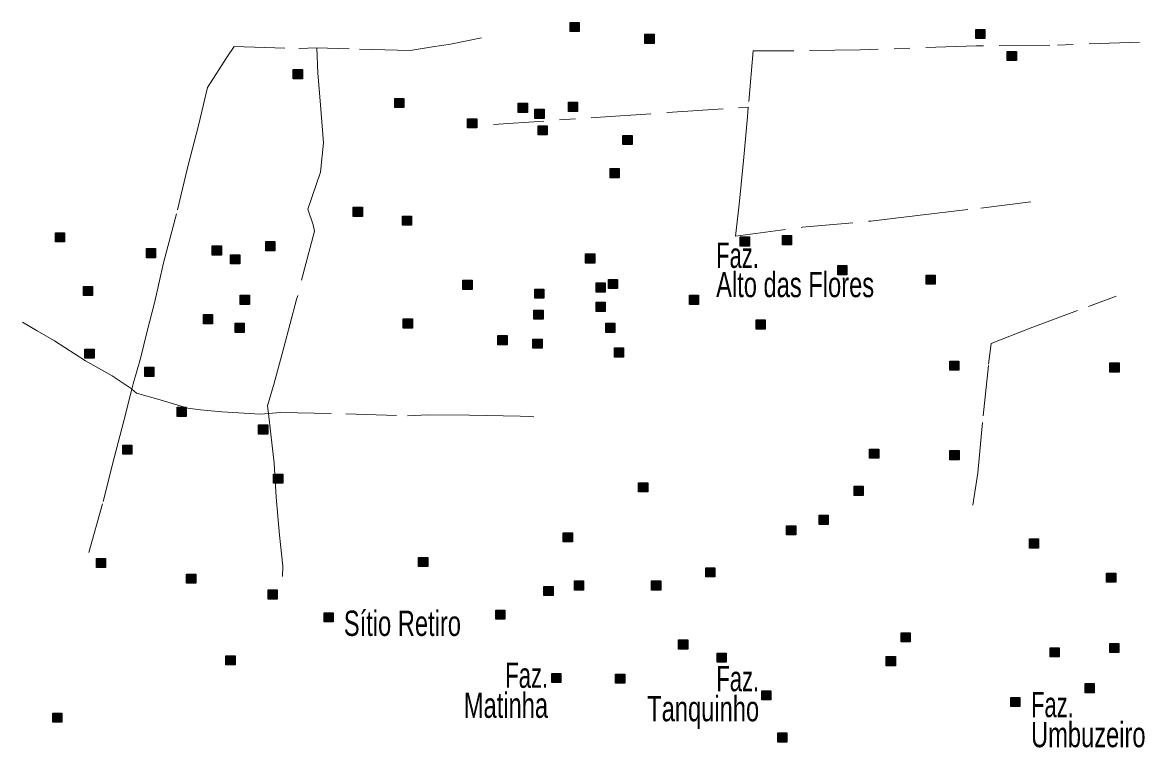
# Model space of a CAD drawing. Extents: x 445.6 to 500, y 8618.1 to 8673.4.
# Drawn here: x 445.63 to 452.73, y 8634.59 to 8639.18 of the extents above; entities that cross this region are included whole.
import ezdxf
from ezdxf.enums import TextEntityAlignment as Align

# ---------------------------------------------------------------- set-up
doc = ezdxf.new("R2010")
doc.units = 0
doc.header["$LTSCALE"] = 0.064
doc.linetypes.add('DOT_DASHED', pattern=[7.7, 5, -1.2, 0.3, -1.2])
doc.layers.add('2', color=7, linetype='Continuous', lineweight=25)
doc.layers.add('22', color=7, linetype='DOT_DASHED', lineweight=13)
doc.layers.add('61', color=7, linetype='Continuous')

msp = doc.modelspace()

# ---------------------------------------------------------------- hatches: boundary and pattern name
at = {"layer": '2'}
for points in [[(449.0969, 8639.1795), (449.1549, 8639.1795), (449.1549, 8639.1215), (449.0969, 8639.1215)], [(451.6615, 8639.1354), (451.7195, 8639.1354), (451.7195, 8639.0774), (451.6615, 8639.0774)], [(449.5698, 8639.105), (449.6278, 8639.105), (449.6278, 8639.047), (449.5698, 8639.047)], [(451.8608, 8638.9965), (451.9188, 8638.9965), (451.9188, 8638.9385), (451.8608, 8638.9385)], [(447.3463, 8638.8814), (447.4043, 8638.8814), (447.4043, 8638.8234), (447.3463, 8638.8234)], [(447.9881, 8638.6985), (448.0461, 8638.6985), (448.0461, 8638.6405), (447.9881, 8638.6405)], [(448.7693, 8638.668), (448.8273, 8638.668), (448.8273, 8638.61), (448.7693, 8638.61)], [(449.0868, 8638.6748), (449.1448, 8638.6748), (449.1448, 8638.6168), (449.0868, 8638.6168)], [(448.4484, 8638.5697), (448.5064, 8638.5697), (448.5064, 8638.5117), (448.4484, 8638.5117)], [(448.874, 8638.6307), (448.932, 8638.6307), (448.932, 8638.5727), (448.874, 8638.5727)], [(448.8943, 8638.5257), (448.9523, 8638.5257), (448.9523, 8638.4677), (448.8943, 8638.4677)], [(449.4313, 8638.4647), (449.4893, 8638.4647), (449.4893, 8638.4067), (449.4313, 8638.4067)], [(449.3503, 8638.2547), (449.4083, 8638.2547), (449.4083, 8638.1967), (449.3503, 8638.1967)], [(447.7262, 8638.0097), (447.7842, 8638.0097), (447.7842, 8637.9517), (447.7262, 8637.9517)], [(448.0366, 8637.9541), (448.0946, 8637.9541), (448.0946, 8637.8961), (448.0366, 8637.8961)], [(445.8421, 8637.8485), (445.9001, 8637.8485), (445.9001, 8637.7905), (445.8421, 8637.7905)], [(447.1721, 8637.793), (447.2301, 8637.793), (447.2301, 8637.735), (447.1721, 8637.735)], [(450.1728, 8637.8226), (450.2308, 8637.8226), (450.2308, 8637.7646), (450.1728, 8637.7646)], [(450.4392, 8637.8313), (450.4972, 8637.8313), (450.4972, 8637.7733), (450.4392, 8637.7733)], [(446.4184, 8637.7485), (446.4764, 8637.7485), (446.4764, 8637.6905), (446.4184, 8637.6905)], [(446.834, 8637.7652), (446.892, 8637.7652), (446.892, 8637.7072), (446.834, 8637.7072)], [(446.9504, 8637.7096), (447.0084, 8637.7096), (447.0084, 8637.6516), (446.9504, 8637.6516)], [(449.1948, 8637.7151), (449.2528, 8637.7151), (449.2528, 8637.6571), (449.1948, 8637.6571)], [(450.7898, 8637.641), (450.8478, 8637.641), (450.8478, 8637.583), (450.7898, 8637.583)], [(451.348, 8637.5812), (451.406, 8637.5812), (451.406, 8637.5232), (451.348, 8637.5232)], [(446.0194, 8637.5095), (446.0774, 8637.5095), (446.0774, 8637.4515), (446.0194, 8637.4515)], [(448.4189, 8637.5484), (448.4769, 8637.5484), (448.4769, 8637.4904), (448.4189, 8637.4904)], [(449.2613, 8637.5317), (449.3193, 8637.5317), (449.3193, 8637.4737), (449.2613, 8637.4737)], [(449.3388, 8637.554), (449.3968, 8637.554), (449.3968, 8637.496), (449.3388, 8637.496)], [(447.0113, 8637.4539), (447.0693, 8637.4539), (447.0693, 8637.3959), (447.0113, 8637.3959)], [(448.8733, 8637.4928), (448.9313, 8637.4928), (448.9313, 8637.4348), (448.8733, 8637.4348)], [(449.8518, 8637.4534), (449.9098, 8637.4534), (449.9098, 8637.3954), (449.8518, 8637.3954)], [(448.8678, 8637.3594), (448.9258, 8637.3594), (448.9258, 8637.3014), (448.8678, 8637.3014)], [(449.2613, 8637.4094), (449.3193, 8637.4094), (449.3193, 8637.3514), (449.2613, 8637.3514)], [(446.7786, 8637.3316), (446.8366, 8637.3316), (446.8366, 8637.2736), (446.7786, 8637.2736)], [(448.0421, 8637.3038), (448.1001, 8637.3038), (448.1001, 8637.2458), (448.0421, 8637.2458)], [(450.2734, 8637.2979), (450.3314, 8637.2979), (450.3314, 8637.2399), (450.2734, 8637.2399)], [(446.9781, 8637.2761), (447.0361, 8637.2761), (447.0361, 8637.2181), (446.9781, 8637.2181)], [(449.3222, 8637.2761), (449.3802, 8637.2761), (449.3802, 8637.2181), (449.3222, 8637.2181)], [(448.6406, 8637.1982), (448.6986, 8637.1982), (448.6986, 8637.1402), (448.6406, 8637.1402)], [(448.8623, 8637.176), (448.9203, 8637.176), (448.9203, 8637.118), (448.8623, 8637.118)], [(446.029, 8637.1132), (446.087, 8637.1132), (446.087, 8637.0552), (446.029, 8637.0552)], [(449.3776, 8637.1204), (449.4356, 8637.1204), (449.4356, 8637.0624), (449.3776, 8637.0624)], [(451.4976, 8637.0365), (451.5556, 8637.0365), (451.5556, 8636.9785), (451.4976, 8636.9785)], [(452.5103, 8637.0255), (452.5683, 8637.0255), (452.5683, 8636.9675), (452.5103, 8636.9675)], [(446.4073, 8636.9981), (446.4653, 8636.9981), (446.4653, 8636.9401), (446.4073, 8636.9401)], [(446.6121, 8636.7446), (446.6701, 8636.7446), (446.6701, 8636.6866), (446.6121, 8636.6866)], [(447.1274, 8636.6334), (447.1854, 8636.6334), (447.1854, 8636.5754), (447.1274, 8636.5754)], [(446.2685, 8636.5056), (446.3265, 8636.5056), (446.3265, 8636.4476), (446.2685, 8636.4476)], [(450.9909, 8636.4807), (451.0489, 8636.4807), (451.0489, 8636.4227), (450.9909, 8636.4227)], [(451.4984, 8636.4709), (451.5564, 8636.4709), (451.5564, 8636.4129), (451.4984, 8636.4129)], [(447.2216, 8636.3221), (447.2796, 8636.3221), (447.2796, 8636.2641), (447.2216, 8636.2641)], [(449.5298, 8636.2673), (449.5878, 8636.2673), (449.5878, 8636.2093), (449.5298, 8636.2093)], [(450.893, 8636.2451), (450.951, 8636.2451), (450.951, 8636.1871), (450.893, 8636.1871)], [(450.6714, 8636.0617), (450.7294, 8636.0617), (450.7294, 8636.0037), (450.6714, 8636.0037)], [(449.0532, 8635.9505), (449.1112, 8635.9505), (449.1112, 8635.8925), (449.0532, 8635.8925)], [(450.4663, 8635.995), (450.5243, 8635.995), (450.5243, 8635.937), (450.4663, 8635.937)], [(452.0014, 8635.9116), (452.0594, 8635.9116), (452.0594, 8635.8536), (452.0014, 8635.8536)], [(448.1388, 8635.7949), (448.1968, 8635.7949), (448.1968, 8635.7369), (448.1388, 8635.7369)], [(446.1022, 8635.7886), (446.1602, 8635.7886), (446.1602, 8635.7306), (446.1022, 8635.7306)], [(449.9544, 8635.7291), (450.0124, 8635.7291), (450.0124, 8635.6711), (449.9544, 8635.6711)], [(446.6717, 8635.6892), (446.7297, 8635.6892), (446.7297, 8635.6312), (446.6717, 8635.6312)], [(452.4898, 8635.6959), (452.5478, 8635.6959), (452.5478, 8635.6379), (452.4898, 8635.6379)], [(447.1871, 8635.5892), (447.2451, 8635.5892), (447.2451, 8635.5312), (447.1871, 8635.5312)], [(448.9313, 8635.6114), (448.9893, 8635.6114), (448.9893, 8635.5534), (448.9313, 8635.5534)], [(449.1247, 8635.6464), (449.1827, 8635.6464), (449.1827, 8635.5884), (449.1247, 8635.5884)], [(449.6119, 8635.6459), (449.6699, 8635.6459), (449.6699, 8635.5879), (449.6119, 8635.5879)], [(447.5417, 8635.4447), (447.5997, 8635.4447), (447.5997, 8635.3867), (447.5417, 8635.3867)], [(448.6265, 8635.4614), (448.6845, 8635.4614), (448.6845, 8635.4034), (448.6265, 8635.4034)], [(451.1901, 8635.3178), (451.2481, 8635.3178), (451.2481, 8635.2598), (451.1901, 8635.2598)], [(449.7826, 8635.2734), (449.8406, 8635.2734), (449.8406, 8635.2154), (449.7826, 8635.2154)], [(452.5091, 8635.2511), (452.5671, 8635.2511), (452.5671, 8635.1931), (452.5091, 8635.1931)], [(446.9211, 8635.1723), (446.9791, 8635.1723), (446.9791, 8635.1143), (446.9211, 8635.1143)], [(450.0264, 8635.19), (450.0844, 8635.19), (450.0844, 8635.132), (450.0264, 8635.132)], [(451.0959, 8635.1678), (451.1539, 8635.1678), (451.1539, 8635.1098), (451.0959, 8635.1098)], [(452.1322, 8635.2234), (452.1902, 8635.2234), (452.1902, 8635.1654), (452.1322, 8635.1654)], [(448.9812, 8635.0612), (449.0392, 8635.0612), (449.0392, 8635.0032), (448.9812, 8635.0032)], [(449.3846, 8635.0567), (449.4426, 8635.0567), (449.4426, 8634.9987), (449.3846, 8634.9987)], [(450.309, 8634.951), (450.367, 8634.951), (450.367, 8634.893), (450.309, 8634.893)], [(452.3532, 8634.9968), (452.4112, 8634.9968), (452.4112, 8634.9388), (452.3532, 8634.9388)], [(451.8838, 8634.9089), (451.9418, 8634.9089), (451.9418, 8634.8509), (451.8838, 8634.8509)], [(445.8252, 8634.8103), (445.8832, 8634.8103), (445.8832, 8634.7523), (445.8252, 8634.7523)], [(450.4098, 8634.6843), (450.4678, 8634.6843), (450.4678, 8634.6263), (450.4098, 8634.6263)]]:
    msp.add_hatch(color=256, dxfattribs=at).paths.add_polyline_path(points)

# ---------------------------------------------------------------- linework, layer by layer
for points in [[(449.0969, 8639.1795), (449.1549, 8639.1795), (449.1549, 8639.1215), (449.0969, 8639.1215)], [(451.6615, 8639.1354), (451.7195, 8639.1354), (451.7195, 8639.0774), (451.6615, 8639.0774)], [(449.5698, 8639.105), (449.6278, 8639.105), (449.6278, 8639.047), (449.5698, 8639.047)], [(451.8608, 8638.9965), (451.9188, 8638.9965), (451.9188, 8638.9385), (451.8608, 8638.9385)], [(447.3463, 8638.8814), (447.4043, 8638.8814), (447.4043, 8638.8234), (447.3463, 8638.8234)], [(447.9881, 8638.6985), (448.0461, 8638.6985), (448.0461, 8638.6405), (447.9881, 8638.6405)], [(448.7693, 8638.668), (448.8273, 8638.668), (448.8273, 8638.61), (448.7693, 8638.61)], [(449.0868, 8638.6748), (449.1448, 8638.6748), (449.1448, 8638.6168), (449.0868, 8638.6168)], [(448.4484, 8638.5697), (448.5064, 8638.5697), (448.5064, 8638.5117), (448.4484, 8638.5117)], [(448.874, 8638.6307), (448.932, 8638.6307), (448.932, 8638.5727), (448.874, 8638.5727)], [(448.8943, 8638.5257), (448.9523, 8638.5257), (448.9523, 8638.4677), (448.8943, 8638.4677)], [(449.4313, 8638.4647), (449.4893, 8638.4647), (449.4893, 8638.4067), (449.4313, 8638.4067)], [(449.3503, 8638.2547), (449.4083, 8638.2547), (449.4083, 8638.1967), (449.3503, 8638.1967)], [(447.7262, 8638.0097), (447.7842, 8638.0097), (447.7842, 8637.9517), (447.7262, 8637.9517)], [(448.0366, 8637.9541), (448.0946, 8637.9541), (448.0946, 8637.8961), (448.0366, 8637.8961)], [(445.8421, 8637.8485), (445.9001, 8637.8485), (445.9001, 8637.7905), (445.8421, 8637.7905)], [(447.1721, 8637.793), (447.2301, 8637.793), (447.2301, 8637.735), (447.1721, 8637.735)], [(450.1728, 8637.8226), (450.2308, 8637.8226), (450.2308, 8637.7646), (450.1728, 8637.7646)], [(450.4392, 8637.8313), (450.4972, 8637.8313), (450.4972, 8637.7733), (450.4392, 8637.7733)], [(446.4184, 8637.7485), (446.4764, 8637.7485), (446.4764, 8637.6905), (446.4184, 8637.6905)], [(446.834, 8637.7652), (446.892, 8637.7652), (446.892, 8637.7072), (446.834, 8637.7072)], [(446.9504, 8637.7096), (447.0084, 8637.7096), (447.0084, 8637.6516), (446.9504, 8637.6516)], [(449.1948, 8637.7151), (449.2528, 8637.7151), (449.2528, 8637.6571), (449.1948, 8637.6571)], [(450.7898, 8637.641), (450.8478, 8637.641), (450.8478, 8637.583), (450.7898, 8637.583)], [(451.348, 8637.5812), (451.406, 8637.5812), (451.406, 8637.5232), (451.348, 8637.5232)], [(446.0194, 8637.5095), (446.0774, 8637.5095), (446.0774, 8637.4515), (446.0194, 8637.4515)], [(448.4189, 8637.5484), (448.4769, 8637.5484), (448.4769, 8637.4904), (448.4189, 8637.4904)], [(449.2613, 8637.5317), (449.3193, 8637.5317), (449.3193, 8637.4737), (449.2613, 8637.4737)], [(449.3388, 8637.554), (449.3968, 8637.554), (449.3968, 8637.496), (449.3388, 8637.496)], [(447.0113, 8637.4539), (447.0693, 8637.4539), (447.0693, 8637.3959), (447.0113, 8637.3959)], [(448.8733, 8637.4928), (448.9313, 8637.4928), (448.9313, 8637.4348), (448.8733, 8637.4348)], [(449.8518, 8637.4534), (449.9098, 8637.4534), (449.9098, 8637.3954), (449.8518, 8637.3954)], [(448.8678, 8637.3594), (448.9258, 8637.3594), (448.9258, 8637.3014), (448.8678, 8637.3014)], [(449.2613, 8637.4094), (449.3193, 8637.4094), (449.3193, 8637.3514), (449.2613, 8637.3514)], [(446.7786, 8637.3316), (446.8366, 8637.3316), (446.8366, 8637.2736), (446.7786, 8637.2736)], [(448.0421, 8637.3038), (448.1001, 8637.3038), (448.1001, 8637.2458), (448.0421, 8637.2458)], [(450.2734, 8637.2979), (450.3314, 8637.2979), (450.3314, 8637.2399), (450.2734, 8637.2399)], [(446.9781, 8637.2761), (447.0361, 8637.2761), (447.0361, 8637.2181), (446.9781, 8637.2181)], [(449.3222, 8637.2761), (449.3802, 8637.2761), (449.3802, 8637.2181), (449.3222, 8637.2181)], [(448.6406, 8637.1982), (448.6986, 8637.1982), (448.6986, 8637.1402), (448.6406, 8637.1402)], [(448.8623, 8637.176), (448.9203, 8637.176), (448.9203, 8637.118), (448.8623, 8637.118)], [(446.029, 8637.1132), (446.087, 8637.1132), (446.087, 8637.0552), (446.029, 8637.0552)], [(449.3776, 8637.1204), (449.4356, 8637.1204), (449.4356, 8637.0624), (449.3776, 8637.0624)], [(451.4976, 8637.0365), (451.5556, 8637.0365), (451.5556, 8636.9785), (451.4976, 8636.9785)], [(452.5103, 8637.0255), (452.5683, 8637.0255), (452.5683, 8636.9675), (452.5103, 8636.9675)], [(446.4073, 8636.9981), (446.4653, 8636.9981), (446.4653, 8636.9401), (446.4073, 8636.9401)], [(446.6121, 8636.7446), (446.6701, 8636.7446), (446.6701, 8636.6866), (446.6121, 8636.6866)], [(447.1274, 8636.6334), (447.1854, 8636.6334), (447.1854, 8636.5754), (447.1274, 8636.5754)], [(446.2685, 8636.5056), (446.3265, 8636.5056), (446.3265, 8636.4476), (446.2685, 8636.4476)], [(450.9909, 8636.4807), (451.0489, 8636.4807), (451.0489, 8636.4227), (450.9909, 8636.4227)], [(451.4984, 8636.4709), (451.5564, 8636.4709), (451.5564, 8636.4129), (451.4984, 8636.4129)], [(447.2216, 8636.3221), (447.2796, 8636.3221), (447.2796, 8636.2641), (447.2216, 8636.2641)], [(449.5298, 8636.2673), (449.5878, 8636.2673), (449.5878, 8636.2093), (449.5298, 8636.2093)], [(450.893, 8636.2451), (450.951, 8636.2451), (450.951, 8636.1871), (450.893, 8636.1871)], [(450.6714, 8636.0617), (450.7294, 8636.0617), (450.7294, 8636.0037), (450.6714, 8636.0037)], [(449.0532, 8635.9505), (449.1112, 8635.9505), (449.1112, 8635.8925), (449.0532, 8635.8925)], [(450.4663, 8635.995), (450.5243, 8635.995), (450.5243, 8635.937), (450.4663, 8635.937)], [(452.0014, 8635.9116), (452.0594, 8635.9116), (452.0594, 8635.8536), (452.0014, 8635.8536)], [(448.1388, 8635.7949), (448.1968, 8635.7949), (448.1968, 8635.7369), (448.1388, 8635.7369)], [(446.1022, 8635.7886), (446.1602, 8635.7886), (446.1602, 8635.7306), (446.1022, 8635.7306)], [(449.9544, 8635.7291), (450.0124, 8635.7291), (450.0124, 8635.6711), (449.9544, 8635.6711)], [(446.6717, 8635.6892), (446.7297, 8635.6892), (446.7297, 8635.6312), (446.6717, 8635.6312)], [(452.4898, 8635.6959), (452.5478, 8635.6959), (452.5478, 8635.6379), (452.4898, 8635.6379)], [(447.1871, 8635.5892), (447.2451, 8635.5892), (447.2451, 8635.5312), (447.1871, 8635.5312)], [(448.9313, 8635.6114), (448.9893, 8635.6114), (448.9893, 8635.5534), (448.9313, 8635.5534)], [(449.1247, 8635.6464), (449.1827, 8635.6464), (449.1827, 8635.5884), (449.1247, 8635.5884)], [(449.6119, 8635.6459), (449.6699, 8635.6459), (449.6699, 8635.5879), (449.6119, 8635.5879)], [(447.5417, 8635.4447), (447.5997, 8635.4447), (447.5997, 8635.3867), (447.5417, 8635.3867)], [(448.6265, 8635.4614), (448.6845, 8635.4614), (448.6845, 8635.4034), (448.6265, 8635.4034)], [(451.1901, 8635.3178), (451.2481, 8635.3178), (451.2481, 8635.2598), (451.1901, 8635.2598)], [(449.7826, 8635.2734), (449.8406, 8635.2734), (449.8406, 8635.2154), (449.7826, 8635.2154)], [(452.5091, 8635.2511), (452.5671, 8635.2511), (452.5671, 8635.1931), (452.5091, 8635.1931)], [(446.9211, 8635.1723), (446.9791, 8635.1723), (446.9791, 8635.1143), (446.9211, 8635.1143)], [(450.0264, 8635.19), (450.0844, 8635.19), (450.0844, 8635.132), (450.0264, 8635.132)], [(451.0959, 8635.1678), (451.1539, 8635.1678), (451.1539, 8635.1098), (451.0959, 8635.1098)], [(452.1322, 8635.2234), (452.1902, 8635.2234), (452.1902, 8635.1654), (452.1322, 8635.1654)], [(448.9812, 8635.0612), (449.0392, 8635.0612), (449.0392, 8635.0032), (448.9812, 8635.0032)], [(449.3846, 8635.0567), (449.4426, 8635.0567), (449.4426, 8634.9987), (449.3846, 8634.9987)], [(450.309, 8634.951), (450.367, 8634.951), (450.367, 8634.893), (450.309, 8634.893)], [(452.3532, 8634.9968), (452.4112, 8634.9968), (452.4112, 8634.9388), (452.3532, 8634.9388)], [(451.8838, 8634.9089), (451.9418, 8634.9089), (451.9418, 8634.8509), (451.8838, 8634.8509)], [(445.8252, 8634.8103), (445.8832, 8634.8103), (445.8832, 8634.7523), (445.8252, 8634.7523)], [(450.4098, 8634.6843), (450.4678, 8634.6843), (450.4678, 8634.6263), (450.4098, 8634.6263)]]:
    msp.add_lwpolyline(points, close=True, dxfattribs=at)
at = {"layer": '22'}
for points in [[(448.5363, 8639.0822), (448.3412, 8639.0428), (448.2263, 8639.0245), (448.0854, 8639.0011), (447.6991, 8639.0115), (447.4956, 8639.0193)], [(446.3264, 8636.8591), (446.3349, 8636.8922), (446.3795, 8637.053), (446.4219, 8637.2255), (446.4714, 8637.4136), (446.5259, 8637.6586), (446.6154, 8637.9941), (446.6773, 8638.2589), (446.7495, 8638.5353), (446.804, 8638.7679), (446.9279, 8638.961), (446.9728, 8639.0269), (447.3816, 8639.0145), (447.4956, 8639.0193)], [(447.4956, 8639.0193), (447.5008, 8638.8577), (447.5165, 8638.6831), (447.5373, 8638.4182), (447.519, 8638.2331), (447.4381, 8637.9985), (447.472, 8637.8994), (447.4799, 8637.8583), (447.3676, 8637.4256), (447.2867, 8637.1233), (447.2263, 8636.8975), (447.1845, 8636.7541), (447.1902, 8636.7054)], [(452.6984, 8639.0546), (452.1311, 8639.035), (451.6655, 8639.0317), (450.9309, 8639.0055), (450.4347, 8638.9988), (450.2543, 8638.9988), (450.2235, 8638.6442)], [(448.612, 8638.5328), (449.2887, 8638.5809), (449.7446, 8638.6112), (450.161, 8638.6385), (450.2235, 8638.6442)], [(450.2235, 8638.6442), (450.2182, 8638.5828), (450.1953, 8638.3274), (450.1653, 8638.0273), (450.1423, 8637.8275), (450.5653, 8637.8832), (450.9982, 8637.9225), (451.2933, 8637.9585), (451.6933, 8638.0044), (452.0237, 8638.0471)], [(451.6435, 8636.1263), (451.6748, 8636.3307), (451.7087, 8636.6905), (451.7426, 8637.0165), (451.7596, 8637.1478), (452.0054, 8637.2451), (452.3751, 8637.3833), (452.5489, 8637.4468)], [(446.3264, 8636.8591), (446.3214, 8636.8634), (446.2023, 8636.9444), (446.033, 8637.0396), (445.8376, 8637.1658), (445.7279, 8637.2277), (445.634, 8637.2823)], [(446.0535, 8635.8265), (446.1439, 8636.1481), (446.2133, 8636.4253), (446.2754, 8636.6595), (446.3264, 8636.8591)], [(446.3264, 8636.8591), (446.3548, 8636.8349), (446.505, 8636.792), (446.679, 8636.7397), (446.76, 8636.7278), (446.8958, 8636.7158), (447.139, 8636.7016), (447.1902, 8636.7054)], [(447.1902, 8636.7054), (447.2653, 8636.7111), (447.6797, 8636.7025), (448.0682, 8636.6906), (448.1993, 8636.6978), (448.4615, 8636.6954), (448.7808, 8636.6882), (448.8422, 8636.6858), (448.8669, 8636.6833)], [(447.1902, 8636.7054), (447.2054, 8636.5742), (447.2262, 8636.3903), (447.2392, 8636.1766), (447.2601, 8635.9354), (447.281, 8635.7399), (447.2794, 8635.6734)]]:
    msp.add_lwpolyline(points, dxfattribs=at)

# ---------------------------------------------------------------- texts
at = {"layer": '61'}
for s, width, p in [('Faz.', 0.65, (450.0205, 8637.6264)), ('Alto das Flores', 0.7, (450.0205, 8637.4414)), ('Sítio Retiro', 0.7, (447.6662, 8635.2981)), ('Faz.', 0.65, (452.0116, 8634.7841)), ('Umbuzeiro', 0.7, (452.0116, 8634.5941))]:
    msp.add_text(s, height=0.16, dxfattribs=dict(at, width=width)).set_placement(p)
for s, width, p in [('Faz.', 0.65, (448.9577, 8634.9699)), ('Faz.', 0.65, (450.2923, 8634.9482)), ('Matinha', 0.7, (448.9577, 8634.7799)), ('Tanquinho', 0.7, (450.2923, 8634.7582))]:
    msp.add_text(s, height=0.16, dxfattribs=dict(at, width=width)).set_placement(p, align=Align.RIGHT)

doc.saveas('drawing.dxf')
